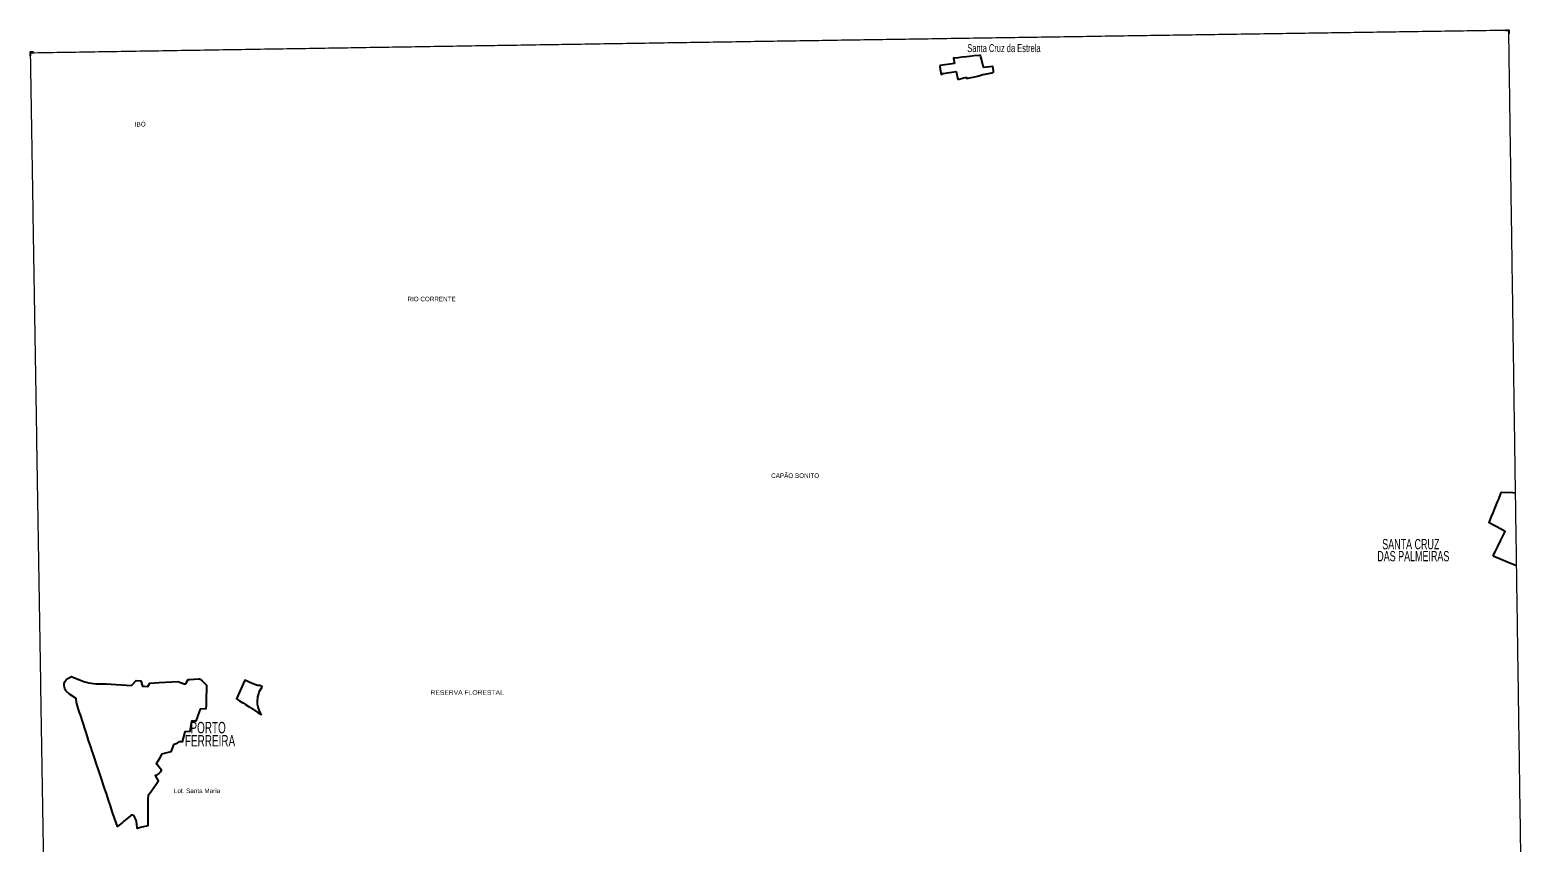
# Model space of a CAD drawing. Extents: x 241.4 to 267.7, y 7565 to 7593.1.
# Drawn here: x 241.42 to 267.7, y 7578.89 to 7593.12 of the extents above; entities that cross this region are included whole.
import ezdxf
from ezdxf.enums import TextEntityAlignment as Align

# ---------------------------------------------------------------- set-up
doc = ezdxf.new("R2010")
doc.units = 0
doc.header["$LTSCALE"] = 0.032
doc.layers.add('41', color=7, linetype='Continuous', lineweight=25)
doc.layers.add('63', color=7, linetype='Continuous', lineweight=13)
doc.layers.add('61', color=7, linetype='Continuous')

msp = doc.modelspace()

# ---------------------------------------------------------------- linework, layer by layer
at = {"layer": '41'}
for points in [[(257.5942, 7592.5365), (257.3458, 7592.4972), (257.3385, 7592.4894), (257.3443, 7592.433), (257.3608, 7592.3436)], [(257.9356, 7592.6659), (257.8593, 7592.6587), (257.8026, 7592.6518), (257.7317, 7592.6432), (257.6616, 7592.6347), (257.5757, 7592.6242), (257.5942, 7592.5365)], [(258.0676, 7592.6113), (258.0574, 7592.6519), (258.0497, 7592.6723), (258.0346, 7592.6752), (257.9356, 7592.6659)], [(258.251, 7592.3693), (258.2603, 7592.3711), (258.2747, 7592.3824), (258.2767, 7592.405), (258.2662, 7592.482), (258.1053, 7592.4608), (258.0676, 7592.6113)], [(257.3608, 7592.3436), (257.3919, 7592.3602), (257.6239, 7592.3954), (257.6536, 7592.2544)], [(257.6536, 7592.2544), (257.7333, 7592.2747), (257.8038, 7592.2927)], [(257.8038, 7592.2927), (257.8071, 7592.2772), (257.8134, 7592.2737), (257.8882, 7592.2885)], [(257.8882, 7592.2885), (257.9533, 7592.3014), (258.0182, 7592.3185)], [(258.0182, 7592.3185), (258.0932, 7592.3383), (258.134, 7592.3463), (258.251, 7592.3693)], [(267.0622, 7584.7756), (267.0983, 7584.8644), (267.1097, 7584.8867)], [(267.1097, 7584.8867), (267.1216, 7584.9101), (267.1576, 7585.0053)], [(267.1576, 7585.0053), (267.1675, 7585.0337), (267.3646, 7585.023), (267.4129, 7585.0209)], [(267.0526, 7584.4416), (266.9517, 7584.495), (266.9889, 7584.5948)], [(266.9889, 7584.5948), (266.9934, 7584.6068), (267.019, 7584.6697), (267.0622, 7584.7756)], [(267.0226, 7583.9132), (267.0399, 7583.9553), (267.0568, 7583.9901), (267.1006, 7584.0805), (267.1489, 7584.18), (267.1953, 7584.2759), (267.2289, 7584.3451), (267.1364, 7584.3968)], [(267.1364, 7584.3968), (267.1207, 7584.4056), (267.0526, 7584.4416)], [(267.4317, 7583.7405), (267.2812, 7583.7997), (267.0226, 7583.9132)], [(242.5818, 7580.2693), (242.5558, 7580.3468), (242.5211, 7580.4504), (242.5057, 7580.4961), (242.4846, 7580.559), (242.4577, 7580.6391), (242.4371, 7580.7007), (242.434, 7580.7108), (242.4038, 7580.8091), (242.3776, 7580.8945), (242.3535, 7580.9728), (242.3423, 7581.0063), (242.3001, 7581.1332), (242.2835, 7581.174), (242.2664, 7581.2293), (242.235, 7581.3307), (242.2329, 7581.3469), (242.2232, 7581.4209), (242.1099, 7581.4944), (242.0521, 7581.5463), (242.0365, 7581.5649), (242.0247, 7581.5982), (242.0159, 7581.6432), (242.0173, 7581.6819), (242.0254, 7581.7126), (242.0319, 7581.7207), (242.0319, 7581.7255), (242.0505, 7581.7466), (242.0783, 7581.7686), (242.1445, 7581.8058), (242.1546, 7581.8016), (242.3418, 7581.7231), (242.3757, 7581.711), (242.4445, 7581.6956), (242.5691, 7581.6786), (242.7472, 7581.6762), (243.1954, 7581.6471), (243.2723, 7581.7339), (243.3557, 7581.7308), (243.3857, 7581.6364), (243.4179, 7581.6349), (243.4773, 7581.6284), (243.4816, 7581.6293), (243.5154, 7581.6881), (243.6751, 7581.7), (243.8971, 7581.7136), (244.0032, 7581.7188), (244.0532, 7581.7004), (244.1325, 7581.6707), (244.1419, 7581.6834), (244.1846, 7581.7543), (244.2066, 7581.7504), (244.3706, 7581.7659), (244.384, 7581.7649), (244.3938, 7581.759), (244.4288, 7581.7267), (244.4977, 7581.6602), (244.5037, 7581.6542), (244.5071, 7581.6482), (244.5034, 7581.569), (244.4981, 7581.457), (244.4972, 7581.3028), (244.4955, 7581.2386), (244.3972, 7581.2351), (244.377, 7581.1855), (244.3215, 7581.0237), (244.2421, 7581.0227), (244.2119, 7580.8441), (244.1283, 7580.8373), (244.0819, 7580.6612), (244.0215, 7580.6624), (243.9991, 7580.6412), (243.9753, 7580.6267), (243.9418, 7580.613), (243.9295, 7580.611), (243.8843, 7580.4871), (243.7179, 7580.444), (243.6816, 7580.3731), (243.6227, 7580.2759), (243.6469, 7580.257), (243.7211, 7580.1719), (243.6978, 7580.1316), (243.6743, 7580.1065), (243.6291, 7580.0798), (243.6087, 7580.0729), (243.6584, 7579.9796), (243.6614, 7579.9657), (243.5481, 7579.8023), (243.4849, 7579.7234), (243.4818, 7579.6623), (243.4797, 7579.3902), (243.4789, 7579.2905), (243.4817, 7579.1922), (243.3524, 7579.1615), (243.2962, 7579.1431), (243.2941, 7579.1575), (243.2884, 7579.2222), (243.2812, 7579.2643), (243.273, 7579.2885), (243.2739, 7579.2934), (243.2536, 7579.3355)], [(245.3059, 7581.6857), (245.1768, 7581.7387), (245.1493, 7581.6792), (245.1252, 7581.6269), (245.0282, 7581.4166), (245.0849, 7581.3812)], [(245.4688, 7581.1333), (245.435, 7581.2045), (245.4083, 7581.2708), (245.3985, 7581.3226), (245.3961, 7581.3615), (245.4043, 7581.4491), (245.4077, 7581.4653), (245.42, 7581.5079), (245.4281, 7581.5311), (245.4356, 7581.5477), (245.4721, 7581.6112), (245.4811, 7581.6254), (245.4776, 7581.6326), (245.4361, 7581.6495), (245.4003, 7581.6469), (245.3059, 7581.6857)], [(245.0849, 7581.3812), (245.1307, 7581.3525), (245.1477, 7581.3417), (245.1871, 7581.3168), (245.2509, 7581.2765)], [(245.2509, 7581.2765), (245.2893, 7581.2522), (245.2921, 7581.2503), (245.4037, 7581.1757)], [(245.4037, 7581.1757), (245.4479, 7581.1462), (245.4688, 7581.1333)], [(243.2536, 7579.3355), (243.2289, 7579.3723), (243.2238, 7579.3797), (243.2057, 7579.3805), (243.1938, 7579.3775), (243.187, 7579.3744), (243.1767, 7579.3694), (243.0505, 7579.2658), (243.0368, 7579.2513), (242.9467, 7579.1796), (242.8666, 7579.41), (242.8612, 7579.4276), (242.8209, 7579.5567), (242.7916, 7579.6439), (242.7588, 7579.7419), (242.7222, 7579.851), (242.6503, 7580.0653), (242.614, 7580.1733), (242.5818, 7580.2693)]]:
    msp.add_lwpolyline(points, dxfattribs=at)
at = {"layer": '63', "lineweight": 25}
for points in [[(267.3005, 7593.0517), (267.3005, 7593.1133), (267.2398, 7593.1133)], [(241.4794, 7592.7299), (241.4178, 7592.7299), (241.4178, 7592.6692)]]:
    msp.add_lwpolyline(points, dxfattribs=at)
at = {"layer": '63'}
for points in [[(241.4274, 7592.7219), (241.9553, 7592.7304), (242.4833, 7592.7389), (243.0112, 7592.7474), (243.5392, 7592.7559), (244.0671, 7592.7643), (244.595, 7592.7728), (245.123, 7592.7812), (245.6509, 7592.7896), (246.1788, 7592.798), (246.7068, 7592.8064), (247.2347, 7592.8148), (247.7626, 7592.8231), (248.2905, 7592.8314), (248.8185, 7592.8397), (249.3464, 7592.848), (249.8743, 7592.8563), (250.4022, 7592.8645), (250.9301, 7592.8728), (251.4581, 7592.881), (251.986, 7592.8892), (252.5139, 7592.8974), (253.0418, 7592.9055), (253.5697, 7592.9137), (254.0976, 7592.9218), (254.6255, 7592.9299), (255.1534, 7592.938), (255.6813, 7592.9461), (256.2092, 7592.9542), (256.7371, 7592.9622), (257.265, 7592.9702), (257.7929, 7592.9782), (258.3208, 7592.9862), (258.8487, 7592.9942), (259.3766, 7593.0022), (259.9045, 7593.0101), (260.4324, 7593.018), (260.9603, 7593.0259), (261.4882, 7593.0338), (262.0161, 7593.0417), (262.544, 7593.0495), (263.0719, 7593.0574), (263.5997, 7593.0652), (264.1276, 7593.073), (264.6555, 7593.0808), (265.1834, 7593.0885), (265.7113, 7593.0963), (266.2391, 7593.104), (266.767, 7593.1117), (267.2949, 7593.1194)], [(267.7002, 7565.4324), (267.6919, 7565.9974), (267.6836, 7566.5625), (267.6753, 7567.1275), (267.667, 7567.6925), (267.6586, 7568.2576), (267.6503, 7568.8226), (267.642, 7569.3877), (267.6337, 7569.9527), (267.6254, 7570.5178), (267.6171, 7571.0828), (267.6088, 7571.6479), (267.6005, 7572.2129), (267.5922, 7572.778), (267.5839, 7573.343), (267.5757, 7573.9081), (267.5674, 7574.4731), (267.5591, 7575.0382), (267.5508, 7575.6032), (267.5425, 7576.1682), (267.5342, 7576.7333), (267.526, 7577.2983), (267.5177, 7577.8634), (267.5094, 7578.4284), (267.5011, 7578.9935), (267.4929, 7579.5585), (267.4846, 7580.1235), (267.4763, 7580.6886), (267.4681, 7581.2536), (267.4598, 7581.8187), (267.4515, 7582.3837), (267.4433, 7582.9487), (267.435, 7583.5138), (267.4268, 7584.0788), (267.4185, 7584.6439), (267.4102, 7585.2089), (267.402, 7585.7739), (267.3937, 7586.339), (267.3855, 7586.904), (267.3773, 7587.4691), (267.369, 7588.0341), (267.3608, 7588.5991), (267.3525, 7589.1642), (267.3443, 7589.7292), (267.336, 7590.2942), (267.3278, 7590.8593), (267.3196, 7591.4243), (267.3114, 7591.9893), (267.3031, 7592.5544), (267.2949, 7593.1194)], [(241.8778, 7565.0311), (241.8686, 7565.5963), (241.8594, 7566.1614), (241.8501, 7566.7265), (241.8409, 7567.2916), (241.8317, 7567.8568), (241.8224, 7568.4219), (241.8132, 7568.987), (241.804, 7569.5521), (241.7947, 7570.1172), (241.7855, 7570.6824), (241.7763, 7571.2475), (241.7671, 7571.8126), (241.7579, 7572.3777), (241.7486, 7572.9428), (241.7394, 7573.508), (241.7302, 7574.0731), (241.721, 7574.6382), (241.7118, 7575.2033), (241.7026, 7575.7684), (241.6934, 7576.3336), (241.6842, 7576.8987), (241.675, 7577.4638), (241.6658, 7578.0289), (241.6566, 7578.594), (241.6474, 7579.1591), (241.6382, 7579.7243), (241.629, 7580.2894), (241.6198, 7580.8545), (241.6107, 7581.4196), (241.6015, 7581.9847), (241.5923, 7582.5498), (241.5831, 7583.115), (241.5739, 7583.6801), (241.5648, 7584.2452), (241.5556, 7584.8103), (241.5464, 7585.3754), (241.5373, 7585.9405), (241.5281, 7586.5056), (241.5189, 7587.0707), (241.5098, 7587.6359), (241.5006, 7588.201), (241.4914, 7588.7661), (241.4823, 7589.3312), (241.4731, 7589.8963), (241.464, 7590.4614), (241.4548, 7591.0265), (241.4457, 7591.5916), (241.4365, 7592.1567), (241.4274, 7592.7219)]]:
    msp.add_spline(points, degree=3, dxfattribs=at)

# ---------------------------------------------------------------- texts
at = {"layer": '61'}
for s, height, width, p in [('Santa Cruz da Estrela', 0.14, 0.7, (257.8184, 7592.7333)), ('  SANTA CRUZ', 0.18, 0.65, (264.9935, 7584.0321)), ('DAS PALMEIRAS', 0.18, 0.65, (264.9935, 7583.8221)), ('  PORTO', 0.2, 0.65, (244.1283, 7580.8104)), ('FERREIRA', 0.2, 0.65, (244.1283, 7580.5804)), ('Lot. Santa Maria', 0.08, 0.95, (243.9343, 7579.7643))]:
    msp.add_text(s, height=height, dxfattribs=dict(at, width=width)).set_placement(p)
for s, width, p in [('IBÓ', 0.95, (243.3469, 7591.4309)), ('RIO CORRENTE', 0.9, (248.4441, 7588.3726)), ('CAPÃO BONITO', 0.95, (254.807, 7585.2802)), ('RESERVA FLORESTAL', 1.1, (249.0669, 7581.4856))]:
    msp.add_text(s, height=0.08, dxfattribs=dict(at, width=width)).set_placement(p, align=Align.CENTER)

doc.saveas('drawing.dxf')
